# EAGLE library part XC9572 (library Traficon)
XC9572 In-System Programmable CPLD
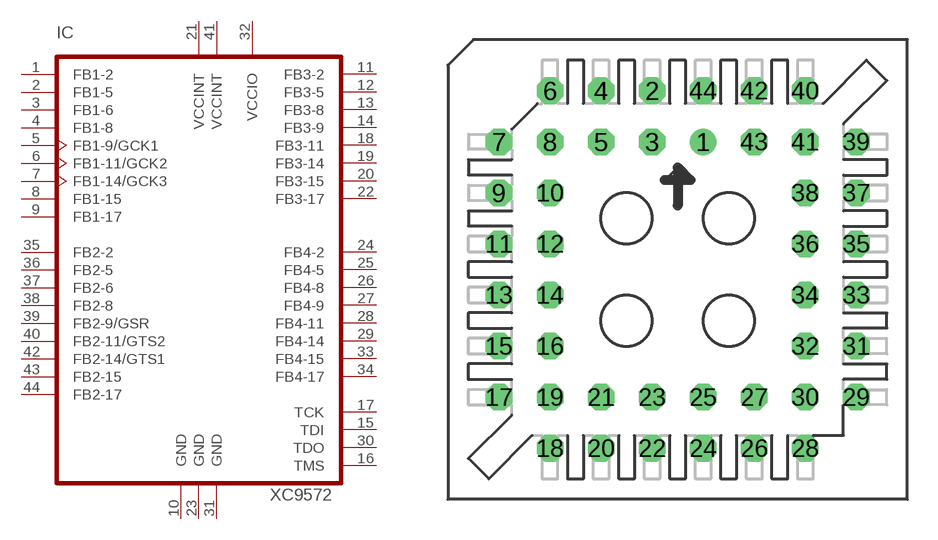
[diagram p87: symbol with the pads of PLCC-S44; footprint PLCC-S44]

Designator prefix IC

## XC9572-15PC44C  [PLCC-S44]
1  FB1-2
2  FB1-5
3  FB1-6
4  FB1-8
5  FB1-9/GCK1
6  FB1-11/GCK2
7  FB1-14/GCK3
8  FB1-15
9  FB1-17
10  GND
11  FB3-2
12  FB3-5
13  FB3-8
14  FB3-9
15  TDI
16  TMS
17  TCK
18  FB3-11
19  FB3-14
20  FB3-15
21  VCCINT
22  FB3-17
23  GND
24  FB4-2
25  FB4-5
26  FB4-8
27  FB4-9
28  FB4-11
29  FB4-14
30  TDO
31  GND
32  VCCIO
33  FB4-15
34  FB4-17
35  FB2-2
36  FB2-5
37  FB2-6
38  FB2-8
39  FB2-9/GSR
40  FB2-11/GTS2
41  VCCINT
42  FB2-14/GTS1
43  FB2-15
44  FB2-17

## Footprint PLCC-S44 (pad centres in mm)
Plastic Leaded Chip Carrier Socked
drill 0.813 round: 1 1.27,6.35
drill 0.813 octagon: 2 -1.27,8.89; 3 -1.27,6.35; 4 -3.81,8.89; 5 -3.81,6.35; 6 -6.35,8.89; 7 -8.89,6.35; 8 -6.35,6.35; 9 -8.89,3.81; 10 -6.35,3.81; 11 -8.89,1.27; 12 -6.35,1.27; 13 -8.89,-1.27; 14 -6.35,-1.27; 15 -8.89,-3.81; 16 -6.35,-3.81; 17 -8.89,-6.35; 18 -6.35,-8.89; 19 -6.35,-6.35; 20 -3.81,-8.89; 21 -3.81,-6.35; 22 -1.27,-8.89; 23 -1.27,-6.35; 24 1.27,-8.89; 25 1.27,-6.35; 26 3.81,-8.89; 27 3.81,-6.35; 28 6.35,-8.89; 29 8.89,-6.35; 30 6.35,-6.35; 31 8.89,-3.81; 32 6.35,-3.81; 33 8.89,-1.27; 34 6.35,-1.27; 35 8.89,1.27; 36 6.35,1.27; 37 8.89,3.81; 38 6.35,3.81; 39 8.89,6.35; 40 6.35,8.89; 41 6.35,6.35; 42 3.81,8.89; 43 3.81,6.35; 44 1.27,8.89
